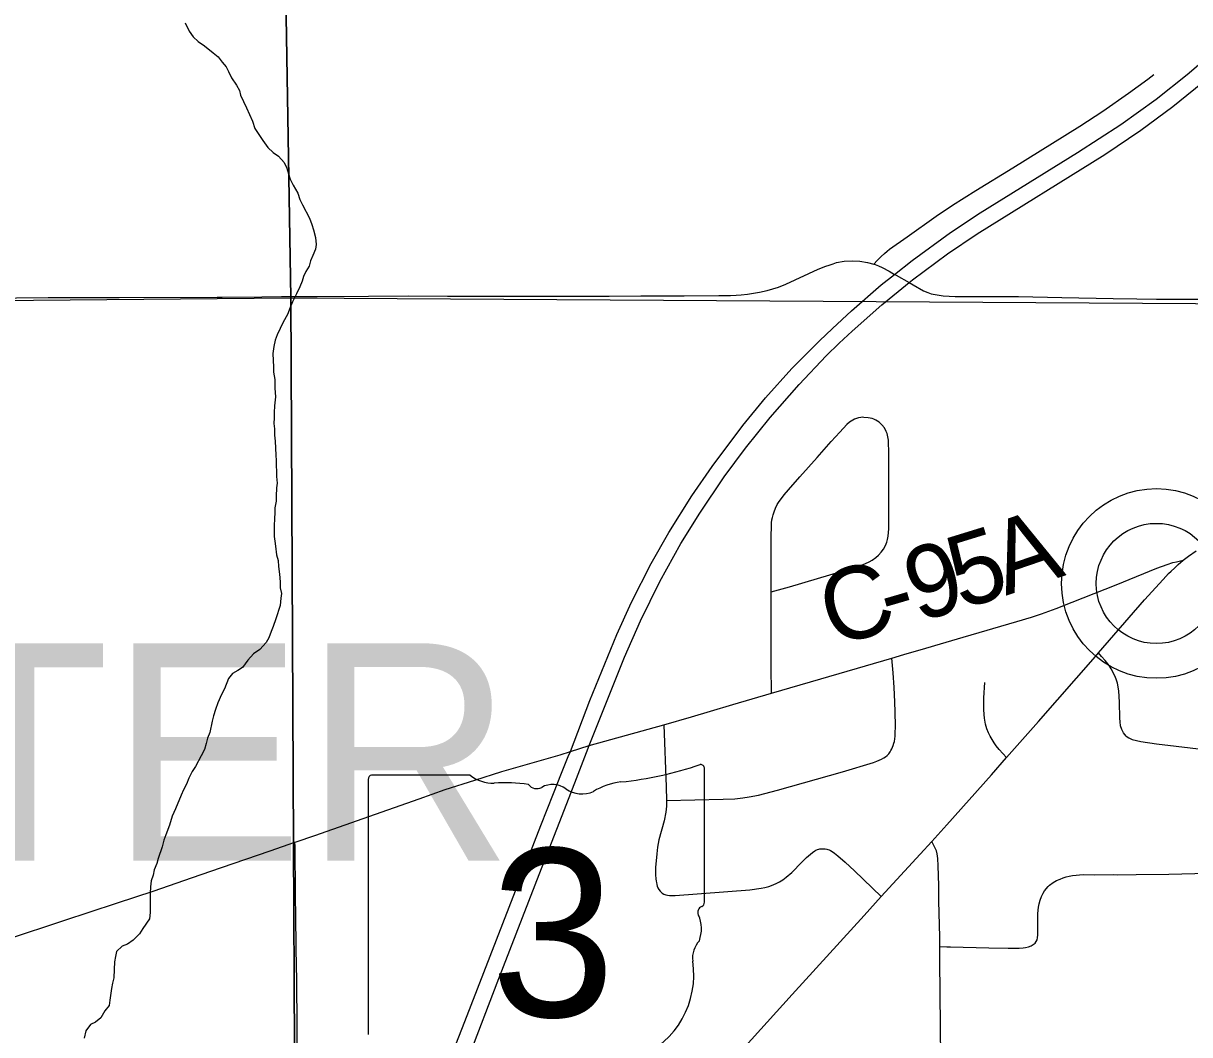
# Model space of a CAD drawing. Extents: x 0 to 34, y 0 to 22.
# Drawn here: x 6.57 to 7.485, y 19.313 to 20.107 of the extents above; entities that cross this region are included whole.
import ezdxf

# ---------------------------------------------------------------- set-up
doc = ezdxf.new("R2010")
doc.units = 0
for name, color, linetype in [('Default', 7, 'Continuous'), ('GM_X_County_Road', 7, 'Continuous'), ('GM_X_County_Road_Text', 7, 'Continuous'), ('GM_X_Minor_River', 7, 'Continuous'), ('GM_X_Section', 7, 'Continuous'), ('GM_X_State_Location', 7, 'Continuous'), ('GM_X_State_Route', 7, 'Continuous'), ('GM_X_State_Shield', 7, 'Continuous'), ('GM_X_Township_Road', 7, 'Continuous'), ('GM_X_Township_Text', 7, 'Continuous'), ('GM_X_Unincorporated', 7, 'Continuous'), ('GM_X_Unincorporated_Location', 7, 'Continuous')]:
    doc.layers.add(name, color=color, linetype=linetype)

msp = doc.modelspace()

# ---------------------------------------------------------------- linework, layer by layer
at = {"layer": 'Default'}
for points in [[(6.76299, 20.89996), (5.65013, 20.89996), (5.65396, 19.92637), (5.65424, 19.88127), (6.77985, 19.89133)], [(7.7825, 20.89996), (6.76299, 20.89996), (6.77985, 19.89133), (7.78202, 19.88507)]]:
    msp.add_lwpolyline(points, close=True, dxfattribs=at)
at = {"layer": 'GM_X_County_Road'}
msp.add_line((7.0139, 19.54016), (7.07251, 19.55638), dxfattribs=at)
for points in [[(6.90771, 19.89271), (6.9214, 19.89267), (6.94613, 19.89263), (6.97709, 19.89272), (6.99568, 19.89271), (7.01112, 19.89262), (7.02967, 19.89274), (7.05432, 19.89301), (7.08846, 19.89297), (7.11565, 19.89321), (7.12485, 19.8933), (7.1293, 19.89354), (7.1332, 19.89376), (7.13823, 19.89425), (7.14747, 19.89579), (7.15356, 19.89717), (7.16251, 19.89978), (7.16829, 19.90202), (7.19366, 19.91374), (7.19959, 19.91616), (7.20229, 19.9171), (7.20532, 19.91816), (7.20805, 19.91898), (7.21406, 19.92002), (7.22015, 19.92035), (7.22625, 19.92001), (7.23231, 19.91904), (7.23722, 19.91773)], [(7.23722, 19.91773), (7.2382, 19.91746), (7.24102, 19.91639), (7.24375, 19.91509), (7.24916, 19.91217), (7.25358, 19.90978)], [(7.25358, 19.90978), (7.25468, 19.90918), (7.26506, 19.90331), (7.2682, 19.90153), (7.27626, 19.89697), (7.27954, 19.89567), (7.28222, 19.8946), (7.28533, 19.89389), (7.29157, 19.89299), (7.30096, 19.89246), (7.32533, 19.89244), (7.35068, 19.89241), (7.38482, 19.8916), (7.42501, 19.89092), (7.4435, 19.89058), (7.45891, 19.89034), (7.47101, 19.89032), (7.47706, 19.89032), (7.508, 19.89034), (7.53366, 19.89013)], [(6.27321, 19.88886), (6.2826, 19.88893), (6.29502, 19.8892), (6.31363, 19.88952), (6.31981, 19.88958), (6.34142, 19.88966), (6.35978, 19.88954), (6.39683, 19.88998), (6.4465, 19.89018), (6.47448, 19.89044), (6.50868, 19.89081), (6.52732, 19.891), (6.53664, 19.89101), (6.56457, 19.89127), (6.58942, 19.8916), (6.62045, 19.89167), (6.64524, 19.89165), (6.72197, 19.89199)], [(6.72197, 19.89199), (6.72596, 19.89201), (6.75697, 19.89221), (6.77249, 19.89234), (6.78491, 19.89241), (6.80044, 19.89247), (6.84076, 19.89258), (6.87178, 19.89284), (6.90283, 19.89272), (6.90771, 19.89271)], [(7.47997, 19.68554), (7.48424, 19.68873), (7.49011, 19.69284)], [(7.25149, 19.60883), (7.2608, 19.61157), (7.27793, 19.61668), (7.28953, 19.62007), (7.30724, 19.62523), (7.34953, 19.63746), (7.36101, 19.64078), (7.36867, 19.64347), (7.38024, 19.64768), (7.39274, 19.65254), (7.42747, 19.66637), (7.45916, 19.67923), (7.46734, 19.68226), (7.47191, 19.68371), (7.47468, 19.68441), (7.47997, 19.68554)], [(7.41351, 19.61281), (7.44959, 19.65443), (7.46424, 19.67051), (7.46853, 19.67503), (7.4706, 19.677), (7.47308, 19.67935), (7.47601, 19.6821), (7.47997, 19.68554)], [(7.34146, 19.53083), (7.36631, 19.55909), (7.41112, 19.61006), (7.41351, 19.61281)], [(7.15701, 19.58122), (7.21015, 19.59668), (7.25149, 19.60883)], [(7.07251, 19.55638), (7.09423, 19.56275), (7.10909, 19.56704), (7.12663, 19.57236), (7.15701, 19.58122)], [(7.28265, 19.46499), (7.29455, 19.4779), (7.32958, 19.51732), (7.34146, 19.53083)], [(7.24304, 19.42167), (7.27353, 19.45509), (7.28265, 19.46499)], [(6.78846, 18.96683), (6.79584, 18.97414), (6.87737, 19.0487), (6.93459, 19.10118), (6.96441, 19.12838), (7.02823, 19.1873), (7.03769, 19.19676), (7.05022, 19.20914), (7.06612, 19.22635), (7.07739, 19.23894), (7.17328, 19.34481), (7.2296, 19.40694), (7.24304, 19.42167)]]:
    msp.add_lwpolyline(points, dxfattribs=at)
at = {"layer": 'GM_X_Minor_River'}
for points in [[(6.697, 20.10708), (6.70013, 20.10067), (6.70323, 20.09615), (6.70708, 20.0924), (6.71207, 20.08905), (6.71899, 20.08345), (6.72283, 20.08046), (6.72593, 20.07632), (6.72902, 20.07256), (6.73097, 20.06879), (6.73332, 20.06388), (6.73719, 20.05824), (6.73953, 20.05409), (6.74034, 20.0503), (6.74503, 20.04049), (6.74973, 20.02992), (6.75171, 20.02425), (6.7552, 20.01859), (6.75791, 20.01483), (6.76179, 20.00918), (6.76602, 20.00544), (6.77024, 20.00246), (6.77449, 19.99758), (6.77683, 19.99305)], [(6.77683, 19.99305), (6.77803, 19.98851), (6.77923, 19.98435), (6.78157, 19.97982), (6.78545, 19.97341), (6.78704, 19.9685), (6.78899, 19.96434), (6.79446, 19.95378), (6.79642, 19.94887), (6.79762, 19.94471), (6.79922, 19.93865), (6.79967, 19.93334), (6.79933, 19.92953), (6.79712, 19.92457), (6.79527, 19.92036), (6.79418, 19.91617), (6.79158, 19.91196), (6.78972, 19.90813), (6.78863, 19.90432), (6.78678, 19.90012), (6.7842, 19.89439), (6.78123, 19.88827), (6.77939, 19.88368), (6.77718, 19.87834), (6.77384, 19.87221), (6.76902, 19.86228), (6.76755, 19.85808), (6.76648, 19.85312), (6.76579, 19.8478), (6.76586, 19.8421), (6.76631, 19.83717), (6.76636, 19.83299), (6.76719, 19.8273), (6.76728, 19.82047), (6.76775, 19.81364), (6.76708, 19.80679), (6.76677, 19.80147), (6.76682, 19.79729), (6.7665, 19.79273), (6.76694, 19.78855), (6.767, 19.78361), (6.76744, 19.77906), (6.76789, 19.77337), (6.76796, 19.76806), (6.7684, 19.76388), (6.76856, 19.75135), (6.76901, 19.74604), (6.76868, 19.74223), (6.76838, 19.73577), (6.76843, 19.73197), (6.76736, 19.72664), (6.76742, 19.72246), (6.76708, 19.71866), (6.76679, 19.7122), (6.76689, 19.70422), (6.76732, 19.70043), (6.76775, 19.69664), (6.7686, 19.68981), (6.7698, 19.68527), (6.77024, 19.68072), (6.77108, 19.67465), (6.77154, 19.66858), (6.7716, 19.66402), (6.77242, 19.65947), (6.77209, 19.65567), (6.7714, 19.64996), (6.76811, 19.63966), (6.76591, 19.63356), (6.76444, 19.62974), (6.7626, 19.62478), (6.76037, 19.62095), (6.75549, 19.61556), (6.7506, 19.61208), (6.7461, 19.60708), (6.74199, 19.60133), (6.73821, 19.599), (6.73406, 19.59666), (6.73107, 19.59282), (6.72775, 19.5848), (6.72553, 19.58021), (6.72257, 19.57372), (6.72074, 19.56838), (6.71928, 19.56342), (6.71819, 19.55923), (6.71641, 19.55046), (6.71457, 19.54588), (6.71348, 19.54169), (6.71201, 19.53711), (6.70942, 19.53214), (6.70496, 19.52372), (6.70235, 19.51989), (6.69976, 19.51453), (6.69792, 19.50995), (6.69569, 19.50536), (6.69385, 19.50116), (6.68942, 19.49046), (6.68683, 19.48473), (6.68464, 19.47787), (6.6817, 19.47023), (6.68023, 19.46603), (6.67878, 19.46069)], [(6.67878, 19.46069), (6.67585, 19.45154), (6.67477, 19.44773), (6.67255, 19.44276), (6.67184, 19.43857), (6.67038, 19.43399), (6.66968, 19.42942), (6.66936, 19.42448), (6.66956, 19.40929), (6.66886, 19.40434), (6.66364, 19.39668), (6.66103, 19.39246), (6.65615, 19.38746), (6.65163, 19.38436), (6.64746, 19.38278), (6.64296, 19.37855), (6.64224, 19.37474), (6.64154, 19.37055), (6.64124, 19.36447), (6.64094, 19.35801), (6.63985, 19.35381), (6.63915, 19.34962), (6.63774, 19.34049), (6.63742, 19.33631), (6.63405, 19.33208), (6.6307, 19.32672), (6.62656, 19.32325), (6.62278, 19.3213), (6.61904, 19.31631), (6.6176, 19.31059)]]:
    msp.add_lwpolyline(points, dxfattribs=at)
at = {"layer": 'GM_X_Section'}
for points in [[(5.65424, 19.88127), (6.77985, 19.89133), (6.78469, 18.87524), (5.64995, 18.87081), (5.64978, 18.89848)], [(6.77985, 19.89133), (7.78202, 19.88507), (7.79585, 18.88307), (6.78469, 18.87524)]]:
    msp.add_lwpolyline(points, close=True, dxfattribs=at)
at = {"layer": 'GM_X_State_Route'}
for points in [[(6.89942, 19.28038), (6.91645, 19.3238), (6.97601, 19.47742), (6.98601, 19.50257), (6.99233, 19.51847), (6.99752, 19.53149), (6.99917, 19.53565), (7.01452, 19.5756), (7.0355, 19.62719), (7.04709, 19.65256), (7.06265, 19.68292), (7.07639, 19.70719), (7.09452, 19.73608), (7.11046, 19.75898), (7.13454, 19.79132), (7.15227, 19.81283), (7.17303, 19.83584), (7.18143, 19.84459), (7.19459, 19.85774), (7.20479, 19.86744), (7.21962, 19.88123), (7.24306, 19.90149), (7.25358, 19.90978), (7.26735, 19.92072), (7.29736, 19.94267), (7.32059, 19.95808), (7.39714, 20.00534), (7.43092, 20.02742), (7.45869, 20.04732), (7.48316, 20.06646), (7.50668, 20.08673)], [(7.0139, 19.54016), (7.02425, 19.56633), (7.04161, 19.60963), (7.05412, 19.63812), (7.06936, 19.66877), (7.08584, 19.69879), (7.10061, 19.72259), (7.11983, 19.75091), (7.13649, 19.77342), (7.15604, 19.79762), (7.17863, 19.82332), (7.19996, 19.84594), (7.21005, 19.85593), (7.22015, 19.86535), (7.2435, 19.88588), (7.26506, 19.90331), (7.26766, 19.90545), (7.29515, 19.9258), (7.3183, 19.94153), (7.41851, 20.00392), (7.44683, 20.02295), (7.47177, 20.04139), (7.5007, 20.06483)], [(6.55768, 19.3884), (6.60177, 19.40308), (6.64312, 19.41654), (6.67261, 19.42627), (6.702, 19.43631), (6.72544, 19.44449), (6.76355, 19.45771), (6.78309, 19.46438), (6.78405, 19.4647), (6.7986, 19.46959), (6.83661, 19.48299), (6.88051, 19.49844), (6.90095, 19.50581), (6.92413, 19.51315), (6.94536, 19.51986), (6.9911, 19.53293), (6.99917, 19.53565), (7.0139, 19.54016)], [(6.81791, 19.05608), (6.82113, 19.06217), (6.82985, 19.07862), (6.83933, 19.09855), (6.84942, 19.11973), (6.85502, 19.13256), (6.86067, 19.14551), (6.87361, 19.17943), (6.88924, 19.22004), (6.90076, 19.25013), (6.91801, 19.29273), (6.92042, 19.29867), (6.94164, 19.35394), (6.97658, 19.44366), (6.99459, 19.48997), (6.99956, 19.50291), (7.00532, 19.51787), (7.01182, 19.53478), (7.0139, 19.54016)]]:
    msp.add_lwpolyline(points, dxfattribs=at)
at = {"layer": 'GM_X_State_Shield'}
for p, q in [((7.10429, 19.41725), (7.10429, 19.52193)), ((6.84062, 19.51353), (6.84062, 19.31341)), ((6.92044, 19.51698), (6.84322, 19.51698)), ((7.10427, 19.41727), (7.10429, 19.41725))]:
    msp.add_line(p, q, dxfattribs=at)
for centre, radius, start, end in [((7.01037, 19.78981), 0.27962, 275.84447, 288.90645), ((7.10137, 19.52237), 0.00294, 351.86209, 97.738), ((6.84365, 19.51396), 0.00305, 98.1301, 188.1301), ((6.93883, 19.54021), 0.02963, 231.61951, 271.11188), ((6.94865, 19.40463), 0.10636, 80.48669, 94.98827), ((6.9728, 19.515), 0.00855, 219.79206, 297.10237), ((6.98534, 19.49187), 0.01777, 54.46668, 119.14113), ((7.04604, 19.45585), 0.05625, 97.34618, 120.76885), ((7.00828, 19.52359), 0.02138, 233.85621, 294.82819), ((7.10361, 19.40956), 0.00454, 107.94398, 210.33697), ((7.10116, 19.41684), 0.00314, 289.60381, 7.73413), ((7.07471, 19.39633), 0.02727, 340.03296, 23.64957), ((7.11481, 19.37344), 0.01984, 136.8065, 186.92959), ((7.02603, 19.36012), 0.06994, 292.30889, 8.98584)]:
    msp.add_arc(centre, radius, start, end, dxfattribs=at)
at = {"layer": 'GM_X_Township_Road'}
for points in [[(7.23722, 19.91773), (7.23998, 19.92059), (7.24294, 19.92372), (7.2457, 19.92623), (7.24768, 19.92803), (7.24952, 19.92947), (7.26333, 19.93933), (7.28624, 19.95534), (7.29902, 19.96399), (7.31727, 19.97559), (7.3462, 19.99347), (7.39877, 20.02604), (7.4169, 20.03784), (7.43709, 20.05203), (7.4521, 20.06286), (7.45699, 20.06654)], [(7.15677, 19.66085), (7.17106, 19.66479), (7.22469, 19.68071), (7.22768, 19.68171), (7.23074, 19.68287), (7.23357, 19.68418), (7.23605, 19.6856), (7.23878, 19.68771), (7.24083, 19.68958), (7.24295, 19.69185), (7.24478, 19.69434), (7.24628, 19.69707), (7.24744, 19.69969), (7.24801, 19.7018), (7.24847, 19.70447), (7.24884, 19.70738), (7.24898, 19.71008), (7.24897, 19.71404), (7.24913, 19.75263), (7.24901, 19.77127), (7.24887, 19.77703), (7.24868, 19.77969), (7.24829, 19.78247), (7.2477, 19.78487), (7.247, 19.78656), (7.24554, 19.7893), (7.24365, 19.79176), (7.24246, 19.79291), (7.24135, 19.79384), (7.24, 19.79465), (7.23869, 19.79545), (7.23722, 19.79614), (7.23581, 19.7966), (7.23436, 19.79705), (7.2328, 19.79735), (7.2294, 19.79758), (7.2282, 19.79765), (7.22707, 19.79752), (7.22524, 19.79718), (7.22371, 19.79673), (7.22219, 19.79614), (7.22087, 19.79548), (7.21826, 19.79379), (7.21613, 19.79197)], [(7.15677, 19.66085), (7.15678, 19.70504), (7.15688, 19.71143), (7.15705, 19.71491), (7.15731, 19.71719), (7.15771, 19.71912), (7.15818, 19.72127), (7.15895, 19.72354), (7.16013, 19.72649), (7.16148, 19.72923), (7.16302, 19.73165), (7.16475, 19.734), (7.16702, 19.73681), (7.17033, 19.74067), (7.17929, 19.75087), (7.19279, 19.76619), (7.20368, 19.77863), (7.21048, 19.78591), (7.21613, 19.79197)], [(7.15701, 19.58122), (7.1567, 19.60216), (7.15677, 19.64585), (7.15677, 19.66085)], [(7.43523, 19.54762), (7.43325, 19.5501), (7.43172, 19.55276), (7.4309, 19.55569), (7.43048, 19.55871), (7.43026, 19.56177), (7.43005, 19.57414), (7.42944, 19.58324), (7.42832, 19.58923), (7.42739, 19.59215), (7.42622, 19.59499), (7.42344, 19.60049), (7.42176, 19.60306), (7.41884, 19.60689), (7.41588, 19.61017), (7.41351, 19.61281)], [(7.07465, 19.49715), (7.11893, 19.49806), (7.12821, 19.4985), (7.13443, 19.49917), (7.13937, 19.49989), (7.14667, 19.50129), (7.16173, 19.5052), (7.21267, 19.51953), (7.23706, 19.52698), (7.23953, 19.5279), (7.2415, 19.52867), (7.24322, 19.5295), (7.24501, 19.53048), (7.24638, 19.53146), (7.24762, 19.53248), (7.2489, 19.53365), (7.25006, 19.53521), (7.25071, 19.53622), (7.25137, 19.53753), (7.2524, 19.54024), (7.25298, 19.54205), (7.25333, 19.54346), (7.25372, 19.5454), (7.25396, 19.54744), (7.25401, 19.5494), (7.25413, 19.55578), (7.25394, 19.56648), (7.25374, 19.57451), (7.25325, 19.5857), (7.2524, 19.5973), (7.25149, 19.60883)], [(7.34146, 19.53083), (7.33549, 19.53721), (7.33335, 19.53998), (7.33168, 19.54231), (7.32997, 19.54487), (7.32845, 19.54755), (7.32723, 19.55025), (7.32603, 19.55324), (7.32533, 19.55526), (7.32487, 19.55695), (7.32454, 19.55857), (7.32406, 19.56174), (7.32377, 19.56458), (7.32355, 19.56835), (7.32349, 19.57753), (7.32446, 19.58961)], [(7.07251, 19.55638), (7.07445, 19.50773), (7.07465, 19.49715)], [(7.43523, 19.54762), (7.43722, 19.54632), (7.44004, 19.54505), (7.44333, 19.54406), (7.4466, 19.54333), (7.45894, 19.54152), (7.50086, 19.53661)], [(7.07465, 19.49715), (7.07464, 19.49528), (7.07457, 19.49268), (7.07428, 19.49028), (7.07395, 19.48802), (7.07265, 19.48102), (7.06856, 19.46612), (7.06747, 19.46058), (7.06687, 19.45535), (7.06635, 19.44987), (7.06603, 19.44485), (7.06606, 19.43888), (7.06625, 19.43569), (7.06648, 19.43389), (7.06664, 19.43269), (7.0669, 19.43127), (7.06729, 19.42983), (7.06774, 19.42858), (7.06848, 19.42722), (7.06953, 19.42596), (7.07032, 19.4252), (7.0712, 19.42443), (7.07261, 19.42359), (7.07409, 19.42312), (7.07536, 19.42281), (7.07683, 19.42259), (7.07914, 19.42259), (7.08135, 19.42254), (7.13985, 19.42704), (7.14896, 19.42827), (7.15168, 19.42882), (7.15487, 19.4297), (7.15702, 19.43046), (7.16051, 19.43187), (7.16317, 19.43325), (7.16575, 19.43486), (7.16834, 19.43694), (7.1728, 19.44063), (7.18086, 19.44877), (7.18437, 19.4523), (7.18747, 19.45504), (7.18925, 19.4564), (7.19098, 19.45763), (7.19187, 19.45811), (7.19305, 19.45863), (7.194, 19.45891), (7.19499, 19.45914), (7.1957, 19.45922), (7.1964, 19.4593)], [(6.78483, 19.30481), (6.78481, 19.33141), (6.78465, 19.34473), (6.7845, 19.35601), (6.78402, 19.38046), (6.7837, 19.40855), (6.78358, 19.41989), (6.78347, 19.42926), (6.78338, 19.43764), (6.78329, 19.44653), (6.78312, 19.46099), (6.78309, 19.46438)], [(7.28896, 19.38257), (7.28893, 19.39016), (7.28821, 19.41815), (7.28822, 19.42748), (7.28813, 19.43042), (7.28768, 19.44586), (7.28734, 19.45148), (7.28687, 19.45519), (7.28633, 19.45748), (7.28569, 19.45921), (7.28405, 19.46234), (7.28265, 19.46499)], [(7.1964, 19.4593), (7.19722, 19.45929), (7.19896, 19.45918), (7.20031, 19.45893), (7.20121, 19.45867), (7.20218, 19.45834), (7.20332, 19.45779), (7.2046, 19.45698), (7.20639, 19.45574), (7.20891, 19.45366), (7.21473, 19.44874), (7.22209, 19.44196), (7.24304, 19.42167)], [(7.36379, 19.38526), (7.36464, 19.38649), (7.36531, 19.38787), (7.3657, 19.38933), (7.36597, 19.39164), (7.36601, 19.39735), (7.36603, 19.40056), (7.36598, 19.40579), (7.36596, 19.4084), (7.36645, 19.41337), (7.36703, 19.41602), (7.36774, 19.4188), (7.36874, 19.42169), (7.37004, 19.42445), (7.37111, 19.42628), (7.37395, 19.42965), (7.37515, 19.43076), (7.37805, 19.43278), (7.38062, 19.4344), (7.38332, 19.43548), (7.38586, 19.43654), (7.3881, 19.43725), (7.39043, 19.43777), (7.39309, 19.43825), (7.39587, 19.43865), (7.39872, 19.43888), (7.40168, 19.43897), (7.41054, 19.4389), (7.42534, 19.43904), (7.42845, 19.43888), (7.44312, 19.43894), (7.46882, 19.43941), (7.49941, 19.44001)], [(7.28896, 19.38257), (7.2945, 19.38233), (7.29748, 19.3822), (7.32753, 19.38155), (7.34267, 19.38119), (7.35133, 19.38129), (7.35428, 19.38144), (7.35636, 19.38174), (7.35861, 19.38229), (7.36061, 19.38306), (7.36235, 19.38407), (7.36379, 19.38526)], [(7.29554, 18.83938), (7.29506, 18.85276), (7.29435, 18.87755), (7.29408, 18.89617), (7.294, 18.91482), (7.29395, 18.92104), (7.29393, 18.92414), (7.29351, 18.9552), (7.29326, 18.97694), (7.29308, 18.9987), (7.29244, 19.05463), (7.29207, 19.08259), (7.29147, 19.11981), (7.29123, 19.13846), (7.29099, 19.1571), (7.29085, 19.17263), (7.2909, 19.19437), (7.29063, 19.21611), (7.29008, 19.26894), (7.289, 19.37152), (7.28896, 19.38257)]]:
    msp.add_lwpolyline(points, dxfattribs=at)
at = {"layer": 'GM_X_Unincorporated'}
for radius in [0.0744, 0.04716]:
    msp.add_circle((7.45894, 19.66733), radius, dxfattribs=at)
at = {"layer": 'GM_X_Unincorporated_Location'}
msp.add_line((7.45894, 19.66733), (7.45894, 19.66733), dxfattribs=at)

# ---------------------------------------------------------------- texts
at = {"layer": 'GM_X_County_Road_Text'}
for s, rotation, p in [('A', 18.89608, (7.3407, 19.6576)), ('5', 17.07829, (7.30564, 19.64679)), ('9', 16.3353, (7.27155, 19.6368)), ('C', 16.30397, (7.20486, 19.61729)), ('-', 16.30395, (7.24932, 19.63029))]:
    msp.add_text(s, height=0.05682, rotation=rotation, dxfattribs=at).set_placement(p)
at = {"layer": 'GM_X_State_Location'}
for s, p in [('s', (6.96949, 19.40017)), ('r', (6.96948, 19.40017))]:
    msp.add_text(s, height=0.000189, dxfattribs=at).set_placement(p)
msp.add_text('3', height=0.000189, rotation=0.00001, dxfattribs=at).set_placement((6.94096, 19.38639))
at = {"layer": 'GM_X_State_Shield'}
msp.add_text('3', height=0.13184, dxfattribs=at).set_placement((6.93637, 19.32752))
at = {"layer": 'GM_X_Township_Text'}
msp.add_text('WOOSTER', height=0.170455, rotation=0.00001, dxfattribs=at).set_placement((5.77664, 19.44998))

doc.saveas('drawing.dxf')
